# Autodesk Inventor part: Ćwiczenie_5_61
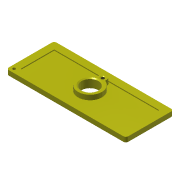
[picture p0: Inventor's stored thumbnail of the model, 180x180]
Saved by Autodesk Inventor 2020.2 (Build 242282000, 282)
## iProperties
Created: 2005-06
Part Number: Ćwiczenie_5_61
Document SubType Name: Modeling
Designer: F.Stasiak
Manufacturer: Standard
Standards Organization: Custom
Density: 1 g/cm^3
Material: Ogólny
Appearance: Żółta
Manager: www.cadconsulting.pl
Company: Fabian Stasiak CAD Consulting
Author: F.Stasiak
Subject: Zbiór ćwiczeń. Autodesk Inventor 2020. Kurs podstawowy
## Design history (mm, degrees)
sketch "Szkic1"
  geometry: L1 (-125, -50)-(125, -50); L2 (125, -50)-(125, 50); L3 (125, 50)-(-125, 50); L4 (-125, 50)-(-125, -50); L5 (0, 50)-(0, -50); 2 further points
  constraints: 10 end point, 3 midpoint, 2 parallel, 1 coincident, 1 horizontal, 1 perpendicular
  dimensions: "d0" = 250 distance of L1.start L1.end; "d1" = 100 distance of L3.end L1.start
extrude "Wyciągnięcie proste1" new body sketch "Szkic1" distance "d2" = 10; taper "d3" = 0 deg
fillet "Zaokrąglenie1" dims "d4" = 5
feature "Skorupa1" dims "d5" = 15, "d6" = 8, "d7" = 1
sketch "Szkic2"
  geometry: L1 (-125, -45)-(-125, 45) reference; L2 (-120, -50)-(120, -50) reference; 1 further point
  dimensions: "d9" = 8 distance from line of point (-117, -42) L1; "d10" = 8 distance from line of L2 point (-117, -42)
hole "Otwory1" sketch "Szkic2" at (-117, -42) diameter "d11" = 6; stored, may be unused: countersink angle "d15" = 90 deg, drill point angle "d17" = 118 deg; dims "d12" = 6, "d13" = 4, "d14" = 2, "d16" = 8
sketch "Szkic6"
  geometry: L1 (220, 0)-(0, 0) reference; L2 (0, 0)-(0, -70) reference; L3 (0, -70)-(220, -70) reference; L4 (220, -70)-(220, 0) reference; L5 (110, 0)-(110, -70); C1 r 25 at (110, -35)
  constraints: 3 midpoint, 2 end point, 1 centre point
  dimensions: "d30" = 50 diameter of C1
extrude "Wyciągnięcie proste5" join sketch "Szkic6" distance "d31" = 10; taper "d32" = 0 deg
sketch "Szkic7"
  geometry: L1 (-8, 23.685)-(-8, 26.685); L2 (8, 26.685)-(8, 23.685); A1 r 25 centre (0, 0) between (-8, 23.685) and (8, 23.685) reference; A2 r 8 centre (0, 26.685) between (8, 26.685) and (-8, 26.685)
  constraints: 4 end point, 4 point on circle, 2 tangent, 1 centre point, 1 parallel, 1 vertical
  dimensions: "d33" = 8 radius of A2; "d34" = 3 distance of L2.start L2.end; "d35" = 0 horizontal distance of A1.centre A2.centre
extrude "Wyciągnięcie proste6" join sketch "Szkic7" distance "d36" = 15; taper "d37" = 5 deg
sketch "Szkic8"
  geometry: A1 r 25 centre (110, -35) between (102, -11.315) and (118, -11.315) reference
hole "Otwory2" sketch "Szkic8" at (110, -35) diameter "d38" = 35; stored, may be unused: countersink angle "d42" = 120 deg, drill point angle "d44" = 118 deg; dims "d39" = 6, "d40" = 40, "d41" = 2, "d43" = 8
sketch "Szkic9"
  geometry: A1 r 8 centre (110, -8.315) between (118, -8.315) and (102, -8.315) reference
hole "Otwory3" sketch "Szkic9" at (110, -8.315) diameter "d45" = 6.647; stored, may be unused: countersink angle "d49" = 120 deg, drill point angle "d51" = 118 deg; dims "d46" = 6, "d47" = 10, "d48" = 2, "d50" = 8
node "Bryła1"
node "Korpusy bryłowe"
node "Korpusy powierzchniowe"
node "Pętla rzutowana3"
